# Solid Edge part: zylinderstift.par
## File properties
Title: Zylinderstift
Subject: Schmiege
Author: rauh
Template: Normal.par
Last saved by: administrator
Revision: 2
Application: Solid Edge
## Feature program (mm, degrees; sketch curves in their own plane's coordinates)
sketch for "unnamed Protrusion 1" plane through (0, 0, 0) normal (0, 0, 1) x-axis (1, 0, 0)
  circle centre (0, 0) radius 1.995
extrude "unnamed Protrusion 1" add finite 9 symmetric
